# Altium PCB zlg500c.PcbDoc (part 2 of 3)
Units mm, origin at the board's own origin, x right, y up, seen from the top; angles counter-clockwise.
Board outline 135.13 x 130.56 mm, 2 copper layers (Top Layer, Bottom Layer); 79 components, 87 nets, 356 pads, 44 vias.
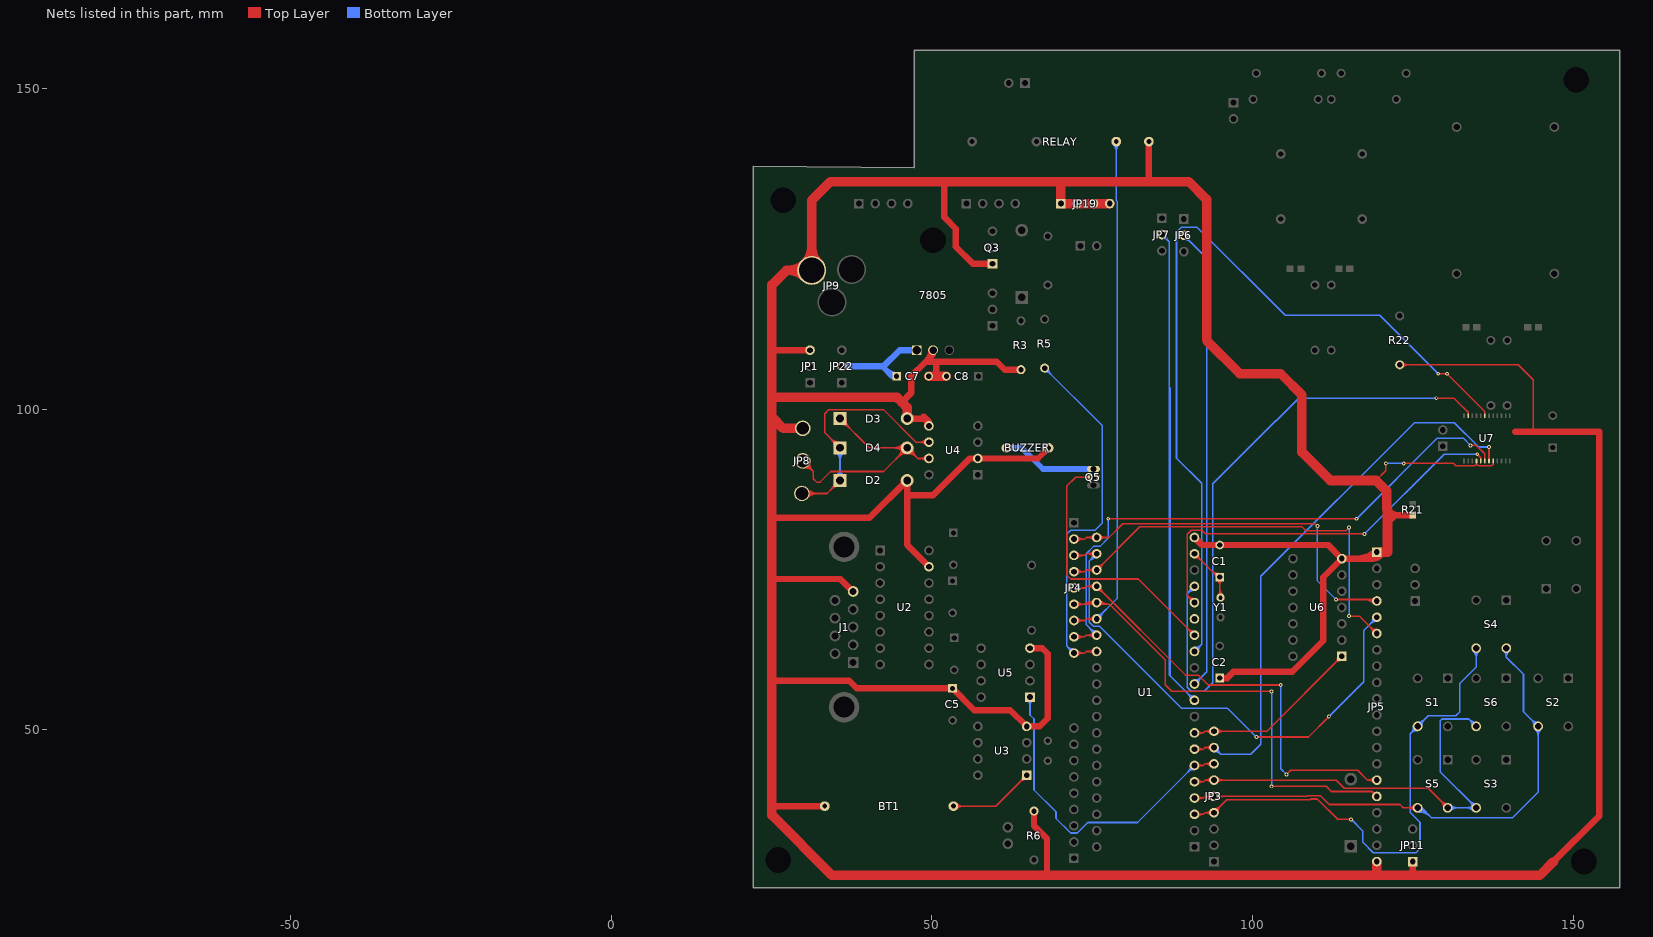
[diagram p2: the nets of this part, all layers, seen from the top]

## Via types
v1: diameter 0.6, hole 0.3, Top Layer to Bottom Layer, 43 vias
v2: diameter 1.27, hole 0.711, Top Layer to Bottom Layer, 1 vias

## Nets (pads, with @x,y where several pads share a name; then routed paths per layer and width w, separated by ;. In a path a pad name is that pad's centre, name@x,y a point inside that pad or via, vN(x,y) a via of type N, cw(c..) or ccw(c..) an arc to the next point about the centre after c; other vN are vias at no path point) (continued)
AP1.2: JP3.4 S1.3 S4.3 U1.3 | length 112.1
  Top Layer w0.254: U1.3@90.932,36.83 92.329,36.83 ; v1(115.367,36.043) 113.259,36.043 110.084,39.218 109.098,39.218 108.971,39.091 95.987,39.091 JP3.4@93.98,37.084 92.583,37.084 ; 91.759,36.83 cw(c91.759,37.573) 91.207,37.077 ccw(c91.759,37.573) 91.759,36.83 ; 91.759,36.83 ccw(c91.759,36.087) 91.207,36.583 cw(c91.759,36.087) 91.759,36.83 ; 92.329,36.83 cw(c92.329,38.085) 91.396,37.246 ccw(c92.329,38.085) 92.329,36.83 ; 92.329,36.83 ccw(c92.329,35.575) 91.396,36.414 cw(c92.329,35.575) 92.329,36.83 ; 92.329,36.83 92.583,37.084 ; 92.583,37.084 cw(c92.583,35.829) 93.516,36.668 ccw(c92.583,35.829) 92.583,37.084 ; 92.583,37.084 ccw(c92.583,38.339) 93.516,37.5 cw(c92.583,38.339) 92.583,37.084 ; 93.153,37.084 cw(c93.153,36.341) 93.705,36.837 ccw(c93.153,36.341) 93.153,37.084 ; 93.153,37.084 ccw(c93.153,37.827) 93.705,37.331 cw(c93.153,37.827) 93.153,37.084 ; 94.61,37.714 cw(c93.98,38.344) 93.98,37.453 ccw(c93.98,38.344) 94.61,37.714 ; 94.61,37.714 ccw(c95.24,37.084) 94.349,37.084 cw(c95.24,37.084) 94.61,37.714 ; 95.044,38.148 cw(c93.98,39.211) 93.98,37.707 ccw(c93.98,39.211) 95.044,38.148 ; 95.044,38.148 ccw(c96.107,37.084) 94.603,37.084 cw(c96.107,37.084) 95.044,38.148
  Bottom Layer w0.254: v1(115.367,36.043) 117.17,34.239 117.17,32.512 118.821,30.861 125.476,30.861 126.111,31.496 126.111,35.585 124.587,37.109 124.587,49.403 S1.3@125.73,50.546 127.381,52.197 131.699,52.197 132.334,52.832 132.334,57.277 134.874,59.817 S4.3@134.874,62.738 ; S1.3@125.095,50.546 cw(c123.562,50.546) 124.646,49.462 cw(c125.73,48.378) S1.3@125.73,49.911 ; S1.3@125.349,50.546 cw(c124.429,50.546) 125.08,49.896 cw(c125.73,49.245) S1.3@125.73,50.165 ; S1.3@125.73,50.927 ccw(c125.73,51.847) 126.38,51.196 ccw(c127.031,50.546) S1.3@126.111,50.546 ; S1.3@125.73,51.181 ccw(c125.73,52.714) 126.814,51.63 ccw(c127.898,50.546) S1.3@126.365,50.546 ; S4.3@134.425,62.289 cw(c133.341,61.205) 134.874,61.205 cw(c136.407,61.205) S4.3@135.323,62.289 ; S4.3@134.605,62.469 cw(c133.954,61.818) 134.874,61.818 cw(c135.794,61.818) S4.3@135.143,62.469
AP1.3: JP3.5 S2.3 S4.4 S5.3 U1.4 | length 123.9
  Top Layer w0.254: U1.4@90.932,39.37 92.329,39.37 ; S5.3@125.281,37.397 ccw(c124.197,36.313) 124.197,37.846 ccw(c124.197,39.379) S5.3@125.281,38.295 ; S5.3@125.461,37.577 ccw(c124.81,36.926) 124.81,37.846 ccw(c124.81,38.766) S5.3@125.461,38.115 ; S5.3@125.73,37.846 123.495,37.846 122.987,38.354 111.963,38.354 110.592,39.726 108.585,39.726 108.483,39.624 JP3.5@93.98,39.624 92.583,39.624 ; 91.759,39.37 cw(c91.759,40.113) 91.207,39.617 ccw(c91.759,40.113) 91.759,39.37 ; 91.759,39.37 ccw(c91.759,38.627) 91.207,39.123 cw(c91.759,38.627) 91.759,39.37 ; 92.329,39.37 cw(c92.329,40.625) 91.396,39.786 ccw(c92.329,40.625) 92.329,39.37 ; 92.329,39.37 ccw(c92.329,38.115) 91.396,38.954 cw(c92.329,38.115) 92.329,39.37 ; 92.329,39.37 92.583,39.624 ; 92.583,39.624 cw(c92.583,38.369) 93.516,39.208 ccw(c92.583,38.369) 92.583,39.624 ; 92.583,39.624 ccw(c92.583,40.879) 93.516,40.04 cw(c92.583,40.879) 92.583,39.624 ; 93.153,39.624 cw(c93.153,38.881) 93.705,39.377 ccw(c93.153,38.881) 93.153,39.624 ; 93.153,39.624 ccw(c93.153,40.367) 93.705,39.871 cw(c93.153,40.367) 93.153,39.624 ; 94.871,39.624 cw(c94.871,40.515) 94.241,39.885 ccw(c94.871,40.515) 94.871,39.624 ; 94.871,39.624 ccw(c94.871,38.733) 94.241,39.363 cw(c94.871,38.733) 94.871,39.624 ; 95.484,39.624 cw(c95.484,41.128) 94.421,40.065 ccw(c95.484,41.128) 95.484,39.624 ; 95.484,39.624 ccw(c95.484,38.12) 94.421,39.183 cw(c95.484,38.12) 95.484,39.624
  Bottom Layer w0.254: S5.3@125.73,37.211 cw(c125.73,34.145) 127.898,36.313 ; S5.3@125.73,37.465 cw(c125.73,35.012) 127.464,36.747 ; S5.3@125.73,37.719 cw(c125.73,35.879) 127.031,37.18 ; S5.3@125.73,37.846 126.365,37.846 127.889,36.322 140.589,36.322 144.526,40.259 S2.3@144.526,50.546 142.24,52.832 142.24,58.674 139.573,61.341 ; S5.3@125.73,37.973 cw(c125.73,36.747) 126.597,37.614 ; S4.4@139.155,62.26 cw(c138.354,61.341) 139.573,61.341 ; S4.4@139.322,62.451 cw(c138.842,61.9) 139.573,61.9 cw(c140.304,61.9) S4.4@139.824,62.451 ; S4.4@139.573,62.738 139.573,61.341 ; S4.4@139.991,62.26 ccw(c140.792,61.341) 139.573,61.341 ; S2.3@143.891,50.546 ccw(c142.358,50.546) 143.442,51.63 ccw(c144.526,52.714) S2.3@144.526,51.181 ; S2.3@144.077,50.097 cw(c142.993,49.013) 144.526,49.013 cw(c146.059,49.013) S2.3@144.975,50.097 ; S2.3@144.145,50.546 ccw(c143.225,50.546) 143.876,51.196 ccw(c144.526,51.847) S2.3@144.526,50.927 ; S2.3@144.257,50.277 cw(c143.606,49.626) 144.526,49.626 cw(c145.446,49.626) S2.3@144.795,50.277
AP1.4: JP3.6 S3.3 S5.4 S6.3 U1.5 | length 119.7
  Top Layer w0.254: U1.5@90.932,41.91 92.329,41.91 ; S5.4@129.794,37.846 ccw(c128.261,37.846) 129.345,38.93 ccw(c130.429,40.014) S5.4@130.429,38.481 ; S5.4@130.048,37.846 ccw(c129.128,37.846) 129.779,38.496 ccw(c130.429,39.147) S5.4@130.429,38.227 ; S5.4@130.429,37.846 127.381,40.894 114.3,40.894 113.03,42.164 JP3.6@93.98,42.164 92.583,42.164 ; 91.759,41.91 cw(c91.759,42.653) 91.207,42.157 ccw(c91.759,42.653) 91.759,41.91 ; 91.759,41.91 ccw(c91.759,41.167) 91.207,41.663 cw(c91.759,41.167) 91.759,41.91 ; 92.329,41.91 cw(c92.329,43.165) 91.396,42.326 ccw(c92.329,43.165) 92.329,41.91 ; 92.329,41.91 ccw(c92.329,40.655) 91.396,41.494 cw(c92.329,40.655) 92.329,41.91 ; 92.329,41.91 92.583,42.164 ; 92.583,42.164 cw(c92.583,40.909) 93.516,41.748 ccw(c92.583,40.909) 92.583,42.164 ; 92.583,42.164 ccw(c92.583,43.419) 93.516,42.58 cw(c92.583,43.419) 92.583,42.164 ; 93.153,42.164 cw(c93.153,41.421) 93.705,41.917 ccw(c93.153,41.421) 93.153,42.164 ; 93.153,42.164 ccw(c93.153,42.907) 93.705,42.411 cw(c93.153,42.907) 93.153,42.164 ; 94.871,42.164 cw(c94.871,43.055) 94.241,42.425 ccw(c94.871,43.055) 94.871,42.164 ; 94.871,42.164 ccw(c94.871,41.273) 94.241,41.903 cw(c94.871,41.273) 94.871,42.164 ; 95.484,42.164 cw(c95.484,43.668) 94.421,42.605 ccw(c95.484,43.668) 95.484,42.164 ; 95.484,42.164 ccw(c95.484,40.66) 94.421,41.723 cw(c95.484,40.66) 95.484,42.164
  Bottom Layer w0.254: S5.4@130.429,37.846 S3.3@134.874,37.846 129.286,43.434 129.286,51.435 129.54,51.689 133.731,51.689 S6.3@134.874,50.546 ; S6.3@134.239,50.546 ccw(c132.706,50.546) 133.79,51.63 ccw(c134.874,52.714) S6.3@134.874,51.181 ; S6.3@134.493,50.546 ccw(c133.573,50.546) 134.224,51.196 ccw(c134.874,51.847) S6.3@134.874,50.927 ; 131.349,37.846 cw(c131.349,38.766) 130.698,38.115 ccw(c131.349,38.766) 131.349,37.846 ; 131.349,37.846 ccw(c131.349,36.926) 130.698,37.577 cw(c131.349,36.926) 131.349,37.846 ; 131.962,37.846 cw(c131.962,39.379) 130.878,38.295 ccw(c131.962,39.379) 131.962,37.846 ; 131.962,37.846 ccw(c131.962,36.313) 130.878,37.397 cw(c131.962,36.313) 131.962,37.846 ; 133.341,37.846 cw(c133.341,36.313) 134.425,37.397 ccw(c133.341,36.313) 133.341,37.846 ; 133.341,37.846 ccw(c133.341,39.379) 134.425,38.295 cw(c133.341,39.379) 133.341,37.846 ; 133.79,38.93 cw(c132.706,37.846) 134.239,37.846 ccw(c132.706,37.846) 133.79,38.93 ; 133.79,38.93 ccw(c134.874,40.014) 134.874,38.481 cw(c134.874,40.014) 133.79,38.93 ; 133.954,37.846 cw(c133.954,36.926) 134.605,37.577 ccw(c133.954,36.926) 133.954,37.846 ; 133.954,37.846 ccw(c133.954,38.766) 134.605,38.115 cw(c133.954,38.766) 133.954,37.846 ; 134.224,38.496 cw(c133.573,37.846) 134.493,37.846 ccw(c133.573,37.846) 134.224,38.496 ; 134.224,38.496 ccw(c134.874,39.147) 134.874,38.227 cw(c134.874,39.147) 134.224,38.496
AP1.5: JP3.7 U1.6 U5.1 | length 75.4
  Top Layer w0.254: U1.6@90.932,44.45 92.329,44.45 ; JP3.7@93.98,44.704 92.583,44.704 ; 91.759,44.45 cw(c91.759,45.193) 91.207,44.697 ccw(c91.759,45.193) 91.759,44.45 ; 91.759,44.45 ccw(c91.759,43.707) 91.207,44.203 cw(c91.759,43.707) 91.759,44.45 ; 92.329,44.45 cw(c92.329,45.705) 91.396,44.866 ccw(c92.329,45.705) 92.329,44.45 ; 92.329,44.45 ccw(c92.329,43.195) 91.396,44.034 cw(c92.329,43.195) 92.329,44.45 ; 92.329,44.45 92.583,44.704 ; 92.583,44.704 cw(c92.583,43.449) 93.516,44.288 ccw(c92.583,43.449) 92.583,44.704 ; 92.583,44.704 ccw(c92.583,45.959) 93.516,45.12 cw(c92.583,45.959) 92.583,44.704 ; 93.153,44.704 cw(c93.153,43.961) 93.705,44.457 ccw(c93.153,43.961) 93.153,44.704 ; 93.153,44.704 ccw(c93.153,45.447) 93.705,44.951 cw(c93.153,45.447) 93.153,44.704
  Bottom Layer w0.254: U5.1@64.837,54.677 cw(c63.774,53.614) 65.278,53.614 cw(c66.782,53.614) U5.1@65.719,54.677 ; U5.1@65.017,54.857 cw(c64.387,54.227) 65.278,54.227 cw(c66.169,54.227) U5.1@65.539,54.857 ; U5.1@65.278,55.118 65.278,52.324 65.913,51.689 65.913,40.64 69.342,37.211 69.342,36.195 71.628,33.909 72.644,33.909 74.295,35.56 82.042,35.56 U1.6@90.932,44.45 ; 89.868,43.386 cw(c90.932,42.323) 90.932,43.827 ccw(c90.932,42.323) 89.868,43.386 ; 89.868,43.386 ccw(c88.805,44.45) 90.309,44.45 cw(c88.805,44.45) 89.868,43.386 ; 90.302,43.82 cw(c90.932,43.19) 90.932,44.081 ccw(c90.932,43.19) 90.302,43.82 ; 90.302,43.82 ccw(c89.672,44.45) 90.563,44.45 cw(c89.672,44.45) 90.302,43.82
AP1.6: JP3.8 U1.7 U7.7 | length 107.9
  Top Layer w0.254: U1.7@90.932,46.99 92.329,46.99 ; JP3.8@93.98,47.244 92.583,47.244 ; U7.7@136.869,91.948 v1(136.869,94.107) ; 91.759,46.99 cw(c91.759,47.733) 91.207,47.237 ccw(c91.759,47.733) 91.759,46.99 ; 91.759,46.99 ccw(c91.759,46.247) 91.207,46.743 cw(c91.759,46.247) 91.759,46.99 ; 92.329,46.99 cw(c92.329,48.245) 91.396,47.406 ccw(c92.329,48.245) 92.329,46.99 ; 92.329,46.99 ccw(c92.329,45.735) 91.396,46.574 cw(c92.329,45.735) 92.329,46.99 ; 92.329,46.99 92.583,47.244 ; 92.583,47.244 cw(c92.583,45.989) 93.516,46.828 ccw(c92.583,45.989) 92.583,47.244 ; 92.583,47.244 ccw(c92.583,48.499) 93.516,47.66 cw(c92.583,48.499) 92.583,47.244 ; 93.153,47.244 cw(c93.153,46.501) 93.705,46.997 ccw(c93.153,46.501) 93.153,47.244 ; 93.153,47.244 ccw(c93.153,47.987) 93.705,47.491 cw(c93.153,47.987) 93.153,47.244
  Bottom Layer w0.254: JP3.8@93.98,47.244 95.047,46.177 99.695,46.177 101.27,47.752 101.27,73.939 125.247,97.917 131.445,97.917 135.255,94.107 v1(136.869,94.107) ; 94.61,46.614 cw(c95.24,47.244) 94.349,47.244 ccw(c95.24,47.244) 94.61,46.614 ; 94.61,46.614 ccw(c93.98,45.984) 93.98,46.875 cw(c93.98,45.984) 94.61,46.614 ; 95.044,46.18 cw(c96.107,47.244) 94.603,47.244 ccw(c96.107,47.244) 95.044,46.18 ; 95.044,46.18 ccw(c93.98,45.117) 93.98,46.621 cw(c93.98,45.117) 95.044,46.18
AP1.7: JP3.9 U1.8 U6.1 | length 56.4
  Top Layer w0.254: U1.8@90.932,49.53 92.329,49.53 ; U6.1@113.919,61.468 102.235,49.784 JP3.9@93.98,49.784 92.583,49.784 ; 91.759,49.53 cw(c91.759,50.273) 91.207,49.777 ccw(c91.759,50.273) 91.759,49.53 ; 91.759,49.53 ccw(c91.759,48.787) 91.207,49.283 cw(c91.759,48.787) 91.759,49.53 ; 92.329,49.53 cw(c92.329,50.785) 91.396,49.946 ccw(c92.329,50.785) 92.329,49.53 ; 92.329,49.53 ccw(c92.329,48.275) 91.396,49.114 cw(c92.329,48.275) 92.329,49.53 ; 92.329,49.53 92.583,49.784 ; 92.583,49.784 cw(c92.583,48.529) 93.516,49.368 ccw(c92.583,48.529) 92.583,49.784 ; 92.583,49.784 ccw(c92.583,51.039) 93.516,50.2 cw(c92.583,51.039) 92.583,49.784 ; 93.153,49.784 cw(c93.153,49.041) 93.705,49.537 ccw(c93.153,49.041) 93.153,49.784 ; 93.153,49.784 ccw(c93.153,50.527) 93.705,50.031 cw(c93.153,50.527) 93.153,49.784 ; 94.871,49.784 cw(c94.871,50.675) 94.241,50.045 ccw(c94.871,50.675) 94.871,49.784 ; 94.871,49.784 ccw(c94.871,48.893) 94.241,49.523 cw(c94.871,48.893) 94.871,49.784 ; 95.484,49.784 cw(c95.484,51.288) 94.421,50.225 ccw(c95.484,51.288) 95.484,49.784 ; 95.484,49.784 ccw(c95.484,48.28) 94.421,49.343 cw(c95.484,48.28) 95.484,49.784 ; 112.855,60.404 cw(c113.919,59.341) 113.919,60.845 ccw(c113.919,59.341) 112.855,60.404 ; 112.855,60.404 ccw(c111.792,61.468) 113.296,61.468 cw(c111.792,61.468) 112.855,60.404 ; U6.1@113.289,60.838 cw(c113.919,60.208) 113.919,61.099 ccw(c113.919,60.208) U6.1@113.289,60.838 ; U6.1@113.289,60.838 ccw(c112.659,61.468) 113.55,61.468 cw(c112.659,61.468) U6.1@113.289,60.838
AP2.0: JP4.2 JP5.4 U1.21 | length 74
  Top Layer w0.254: JP4.2@72.136,79.756 73.787,79.756 74.041,80.01 U1.21@75.692,80.01 77.597,80.01 79.756,82.169 109.728,82.169 v1(110.109,81.788) ; JP4.2@72.397,79.495 cw(c73.027,78.865) 73.027,79.756 cw(c73.027,80.647) JP4.2@72.397,80.017 ; JP4.2@72.577,79.315 cw(c73.64,78.252) 73.64,79.756 cw(c73.64,81.26) JP4.2@72.577,80.197 ; U1.21@75.251,79.569 ccw(c74.188,78.506) 74.188,80.01 ccw(c74.188,81.514) U1.21@75.251,80.451 ; U1.21@75.431,79.749 ccw(c74.801,79.119) 74.801,80.01 ccw(c74.801,80.901) U1.21@75.431,80.271 ; U1.21@75.953,79.749 cw(c76.583,79.119) 76.583,80.01 cw(c76.583,80.901) U1.21@75.953,80.271 ; U1.21@76.133,79.569 cw(c77.196,78.506) 77.196,80.01 cw(c77.196,81.514) U1.21@76.133,80.451 ; v1(113.005,70.333) 119.151,70.333 JP5.4@119.38,70.104 ; 117.324,70.333 cw(c117.324,68.048) JP5.4@118.939,69.663 ; 117.937,70.333 cw(c117.937,68.661) JP5.4@119.119,69.843 ; 118.428,70.333 ccw(c118.428,71.056) JP5.4@118.939,70.545 ; 118.55,70.333 cw(c118.55,69.274) JP5.4@119.299,70.023
  Bottom Layer w0.254: v1(110.109,81.788) 110.109,73.228 v1(113.005,70.333)
AP2.1: JP4.3 JP5.5 U1.22 | length 105.8
  Top Layer w0.254: JP4.3@72.136,77.216 73.787,77.216 74.041,77.47 U1.22@75.692,77.47 ; v1(100.584,48.895) 108.712,48.895 v1(111.887,52.07) ; 73.027,77.216 cw(c73.027,78.107) 72.397,77.477 ccw(c73.027,78.107) 73.027,77.216 ; 73.027,77.216 ccw(c73.027,76.325) 72.397,76.955 cw(c73.027,76.325) 73.027,77.216 ; 73.64,77.216 cw(c73.64,78.72) 72.577,77.657 ccw(c73.64,78.72) 73.64,77.216 ; 73.64,77.216 ccw(c73.64,75.712) 72.577,76.775 cw(c73.64,75.712) 73.64,77.216 ; 74.188,77.47 cw(c74.188,75.966) 75.251,77.029 ccw(c74.188,75.966) 74.188,77.47 ; 74.188,77.47 ccw(c74.188,78.974) 75.251,77.911 cw(c74.188,78.974) 74.188,77.47 ; 74.801,77.47 cw(c74.801,76.579) 75.431,77.209 ccw(c74.801,76.579) 74.801,77.47 ; 74.801,77.47 ccw(c74.801,78.361) 75.431,77.731 cw(c74.801,78.361) 74.801,77.47
  Bottom Layer w0.254: U1.22@75.069,77.47 cw(c73.565,77.47) 74.628,76.406 cw(c75.692,75.343) U1.22@75.692,76.847 ; U1.22@75.323,77.47 cw(c74.432,77.47) 75.062,76.84 cw(c75.692,76.21) U1.22@75.692,77.101 ; U1.22@75.692,77.47 74.549,76.327 74.549,66.802 75.184,66.167 76.124,66.167 88.9,53.391 96.088,53.391 v1(100.584,48.895) ; v1(111.887,52.07) 117.323,57.506 117.323,65.507 JP5.5@119.38,67.564 ; 118.316,66.5 cw(c119.38,65.437) 119.38,66.941 ccw(c119.38,65.437) 118.316,66.5 ; 118.316,66.5 ccw(c117.253,67.564) 118.757,67.564 cw(c117.253,67.564) 118.316,66.5 ; 118.75,66.934 cw(c119.38,66.304) 119.38,67.195 ccw(c119.38,66.304) 118.75,66.934 ; 118.75,66.934 ccw(c118.12,67.564) 119.011,67.564 cw(c118.12,67.564) 118.75,66.934
AP2.2: JP4.4 JP5.6 U1.23 | length 88.1
  Top Layer w0.254: JP4.4@72.136,74.676 73.787,74.676 74.041,74.93 U1.23@75.692,74.93 82.423,81.661 107.721,81.661 108.306,81.077 114.579,81.077 v1(115.062,81.559) ; U1.23@75.692,75.299 ccw(c75.692,76.19) 76.322,75.56 ccw(c76.952,74.93) U1.23@76.061,74.93 ; U1.23@75.692,75.553 ccw(c75.692,77.057) 76.756,75.994 ccw(c77.819,74.93) U1.23@76.315,74.93 ; v1(115.062,67.742) 116.662,67.742 JP5.6@119.38,65.024 ; JP5.6@118.757,65.024 ccw(c117.253,65.024) 118.316,66.088 ccw(c119.38,67.151) JP5.6@119.38,65.647 ; JP5.6@119.011,65.024 ccw(c118.12,65.024) 118.75,65.654 ccw(c119.38,66.284) JP5.6@119.38,65.393 ; 73.027,74.676 cw(c73.027,75.567) 72.397,74.937 ccw(c73.027,75.567) 73.027,74.676 ; 73.027,74.676 ccw(c73.027,73.785) 72.397,74.415 cw(c73.027,73.785) 73.027,74.676 ; 73.64,74.676 cw(c73.64,76.18) 72.577,75.117 ccw(c73.64,76.18) 73.64,74.676 ; 73.64,74.676 ccw(c73.64,73.172) 72.577,74.235 cw(c73.64,73.172) 73.64,74.676 ; 74.188,74.93 cw(c74.188,73.426) 75.251,74.489 ccw(c74.188,73.426) 74.188,74.93 ; 74.188,74.93 ccw(c74.188,76.434) 75.251,75.371 cw(c74.188,76.434) 74.188,74.93 ; 74.801,74.93 cw(c74.801,74.039) 75.431,74.669 ccw(c74.801,74.039) 74.801,74.93 ; 74.801,74.93 ccw(c74.801,75.821) 75.431,75.191 cw(c74.801,75.821) 74.801,74.93
  Bottom Layer w0.254: v1(115.062,67.742) v1(115.062,81.559)
AP2.3: JP4.5 JP5.15 U1.24 | length 94
  Top Layer w0.254: JP4.5@72.136,72.136 73.787,72.136 74.041,72.39 U1.24@75.692,72.39 89.535,58.547 91.542,58.547 93.091,56.998 v1(104.394,56.998) ; U1.24@75.692,71.767 cw(c75.692,70.263) 76.756,71.326 cw(c77.819,72.39) U1.24@76.315,72.39 ; U1.24@75.692,72.021 cw(c75.692,71.13) 76.322,71.76 cw(c76.952,72.39) U1.24@76.061,72.39 ; v1(105.283,43.053) 105.943,43.713 116.383,43.713 117.932,42.164 ; JP5.15@119.38,42.164 117.932,42.164 ; 73.027,72.136 cw(c73.027,73.027) 72.397,72.397 ccw(c73.027,73.027) 73.027,72.136 ; 73.027,72.136 ccw(c73.027,71.245) 72.397,71.875 cw(c73.027,71.245) 73.027,72.136 ; 73.64,72.136 cw(c73.64,73.64) 72.577,72.577 ccw(c73.64,73.64) 73.64,72.136 ; 73.64,72.136 ccw(c73.64,70.632) 72.577,71.695 cw(c73.64,70.632) 73.64,72.136 ; 74.188,72.39 cw(c74.188,70.886) 75.251,71.949 ccw(c74.188,70.886) 74.188,72.39 ; 74.188,72.39 ccw(c74.188,73.894) 75.251,72.831 cw(c74.188,73.894) 74.188,72.39 ; 74.801,72.39 cw(c74.801,71.499) 75.431,72.129 ccw(c74.801,71.499) 74.801,72.39 ; 74.801,72.39 ccw(c74.801,73.281) 75.431,72.651 cw(c74.801,73.281) 74.801,72.39 ; 117.932,42.164 cw(c117.932,40.793) 118.928,41.736 ccw(c117.932,40.793) 117.932,42.164 ; 117.932,42.164 ccw(c117.932,43.535) 118.928,42.592 cw(c117.932,43.535) 117.932,42.164 ; 118.523,42.164 cw(c118.523,41.352) 119.112,41.91 ccw(c118.523,41.352) 118.523,42.164 ; 118.523,42.164 ccw(c118.523,42.976) 119.112,42.418 cw(c118.523,42.976) 118.523,42.164
  Bottom Layer w0.254: v1(104.394,56.998) 104.394,43.942 v1(105.283,43.053)
AP2.4: JP4.6 JP5.16 U1.25 | length 107.2
  Top Layer w0.254: JP4.6@72.136,69.596 73.787,69.596 ; U1.25@75.692,69.85 74.041,69.85 73.787,69.596 ; v1(102.972,41.199) 111.475,41.199 112.288,40.386 118.618,40.386 ; v1(102.972,56.007) 87.376,56.007 86.36,57.023 86.36,60.909 77.673,69.596 ; JP5.16@119.38,39.624 118.618,40.386 ; 73.027,69.596 cw(c73.027,70.487) 72.397,69.857 ccw(c73.027,70.487) 73.027,69.596 ; 73.027,69.596 ccw(c73.027,68.705) 72.397,69.335 cw(c73.027,68.705) 73.027,69.596 ; 73.64,69.596 cw(c73.64,71.1) 72.577,70.037 ccw(c73.64,71.1) 73.64,69.596 ; 73.64,69.596 ccw(c73.64,68.092) 72.577,69.155 cw(c73.64,68.092) 73.64,69.596 ; 73.787,69.596 ccw(c73.787,71.48) 75.219,70.255 cw(c73.787,71.48) 73.787,69.596 ; 73.787,69.596 75.692,69.596 77.673,69.596 ; 74.188,69.85 cw(c74.188,68.346) U1.25@75.251,69.409 ; 74.188,69.85 ccw(c74.188,71.354) 75.251,70.291 cw(c74.188,71.354) 74.188,69.85 ; 74.188,69.85 cw(c74.188,68.346) U1.25@75.251,69.409 ; 74.801,69.85 cw(c74.801,68.959) 75.431,69.589 ccw(c74.801,68.959) 74.801,69.85 ; 74.801,69.85 ccw(c74.801,70.741) 75.431,70.111 cw(c74.801,70.741) 74.801,69.85 ; U1.25@75.251,69.409 ccw(c74.801,68.959) 74.801,69.596 cw(c74.801,68.959) U1.25@75.251,69.409 ; 77.673,69.596 cw(c77.673,71.649) 76.153,70.269 ccw(c77.673,71.649) 77.673,69.596 ; 118.618,40.386 cw(c118.179,39.947) 118.778,39.786 ccw(c118.179,39.947) 118.618,40.386 ; 118.618,40.386 ccw(c119.057,40.825) 119.218,40.226 cw(c119.057,40.825) 118.618,40.386 ; 74.339,69.596 ccw(c74.339,71.008) 75.412,70.09 cw(c74.339,71.008) 74.339,69.596 ; 74.891,69.596 ccw(c74.891,70.536) 75.605,69.925 cw(c74.891,70.536) 74.891,69.596 ; U1.25@75.777,69.927 ccw(c76.526,70.607) 76.526,69.596 cw(c76.526,70.607) U1.25@75.777,69.927 ; U1.25@75.965,70.098 ccw(c77.099,71.128) 77.099,69.596 cw(c77.099,71.128) U1.25@75.965,70.098 ; U1.25@76.133,69.409 cw(c76.583,68.959) 76.583,69.596 ccw(c76.583,68.959) U1.25@76.133,69.409
  Bottom Layer w0.254: v1(102.972,41.199) v1(102.972,56.007)
AP2.5: JP4.7 RELAY.1 U1.26 | length 106
  Top Layer w0.254: JP4.7@72.136,67.056 73.787,67.056 74.041,67.31 U1.26@75.692,67.31 ; 73.027,67.056 cw(c73.027,67.947) 72.397,67.317 ccw(c73.027,67.947) 73.027,67.056 ; 73.027,67.056 ccw(c73.027,66.165) 72.397,66.795 cw(c73.027,66.165) 73.027,67.056 ; 73.64,67.056 cw(c73.64,68.56) 72.577,67.497 ccw(c73.64,68.56) 73.64,67.056 ; 73.64,67.056 ccw(c73.64,65.552) 72.577,66.615 cw(c73.64,65.552) 73.64,67.056 ; 74.188,67.31 cw(c74.188,65.806) 75.251,66.869 ccw(c74.188,65.806) 74.188,67.31 ; 74.188,67.31 ccw(c74.188,68.814) 75.251,67.751 cw(c74.188,68.814) 74.188,67.31 ; 74.801,67.31 cw(c74.801,66.419) 75.431,67.049 ccw(c74.801,66.419) 74.801,67.31 ; 74.801,67.31 ccw(c74.801,68.201) 75.431,67.571 cw(c74.801,68.201) 74.801,67.31
  Bottom Layer w0.254: U1.26@75.692,67.31 78.867,70.485 78.867,132.461 78.74,132.588 RELAY.1@78.74,141.732 ; U1.26@75.692,67.679 ccw(c75.692,68.57) 76.322,67.94 ccw(c76.952,67.31) U1.26@76.061,67.31 ; U1.26@75.692,67.933 ccw(c75.692,69.437) 76.756,68.374 ccw(c77.819,67.31) U1.26@76.315,67.31 ; 78.74,140.199 cw(c80.273,140.199) 79.189,141.283 ccw(c80.273,140.199) 78.74,140.199 ; 78.74,140.199 ccw(c77.207,140.199) 78.291,141.283 cw(c77.207,140.199) 78.74,140.199 ; 78.74,140.812 cw(c79.66,140.812) 79.009,141.463 ccw(c79.66,140.812) 78.74,140.812 ; 78.74,140.812 ccw(c77.82,140.812) 78.471,141.463 cw(c77.82,140.812) 78.74,140.812
AP2.6: JP4.8 U1.27 U7.6 | length 113.1
  Top Layer w0.254: JP4.8@72.136,64.516 73.787,64.516 74.041,64.77 U1.27@75.692,64.77 ; v1(77.495,82.931) v1(116.23,82.931) ; v1(133.985,94.361) 134.899,94.361 136.219,93.041 U7.6@136.219,91.948 ; 73.027,64.516 cw(c73.027,65.407) 72.397,64.777 ccw(c73.027,65.407) 73.027,64.516 ; 73.027,64.516 ccw(c73.027,63.625) 72.397,64.255 cw(c73.027,63.625) 73.027,64.516 ; 73.64,64.516 cw(c73.64,66.02) 72.577,64.957 ccw(c73.64,66.02) 73.64,64.516 ; 73.64,64.516 ccw(c73.64,63.012) 72.577,64.075 cw(c73.64,63.012) 73.64,64.516 ; 74.188,64.77 cw(c74.188,63.266) 75.251,64.329 ccw(c74.188,63.266) 74.188,64.77 ; 74.188,64.77 ccw(c74.188,66.274) 75.251,65.211 cw(c74.188,66.274) 74.188,64.77 ; 74.801,64.77 cw(c74.801,63.879) 75.431,64.509 ccw(c74.801,63.879) 74.801,64.77 ; 74.801,64.77 ccw(c74.801,65.661) 75.431,65.031 cw(c74.801,65.661) 74.801,64.77
  Bottom Layer w0.254: U1.27@75.692,64.77 74.041,66.421 74.041,77.47 75.184,78.613 76.2,78.613 77.495,79.908 v1(77.495,82.931) ; v1(116.23,82.931) 128.803,95.504 132.842,95.504 v1(133.985,94.361) ; 74.628,65.834 cw(c73.565,64.77) 75.069,64.77 ccw(c73.565,64.77) 74.628,65.834 ; 74.628,65.834 ccw(c75.692,66.897) 75.692,65.393 cw(c75.692,66.897) 74.628,65.834 ; 75.062,65.4 cw(c74.432,64.77) 75.323,64.77 ccw(c74.432,64.77) 75.062,65.4 ; 75.062,65.4 ccw(c75.692,66.03) 75.692,65.139 cw(c75.692,66.03) 75.062,65.4
AP2.7: JP4.9 R5.2 U1.28 | length 82.8
  Top Layer w0.254: JP4.9@72.136,61.976 73.787,61.976 74.041,62.23 U1.28@75.692,62.23 ; 73.027,61.976 cw(c73.027,62.867) 72.397,62.237 ccw(c73.027,62.867) 73.027,61.976 ; 73.027,61.976 ccw(c73.027,61.085) 72.397,61.715 cw(c73.027,61.085) 73.027,61.976 ; 73.64,61.976 cw(c73.64,63.48) 72.577,62.417 ccw(c73.64,63.48) 73.64,61.976 ; 73.64,61.976 ccw(c73.64,60.472) 72.577,61.535 cw(c73.64,60.472) 73.64,61.976 ; 74.188,62.23 cw(c74.188,60.726) 75.251,61.789 ccw(c74.188,60.726) 74.188,62.23 ; 74.188,62.23 ccw(c74.188,63.734) 75.251,62.671 cw(c74.188,63.734) 74.188,62.23 ; 74.801,62.23 cw(c74.801,61.339) 75.431,61.969 ccw(c74.801,61.339) 74.801,62.23 ; 74.801,62.23 ccw(c74.801,63.121) 75.431,62.491 cw(c74.801,63.121) 74.801,62.23
  Bottom Layer w0.254: R5.2@67.564,105.853 cw(c67.564,104.47) 68.542,105.448 cw(c69.52,106.426) R5.2@68.137,106.426 ; R5.2@67.564,106.107 cw(c67.564,105.337) 68.109,105.881 cw(c68.653,106.426) R5.2@67.883,106.426 ; R5.2@67.564,106.426 76.581,97.409 76.581,82.296 75.438,81.153 71.628,81.153 70.993,80.518 70.993,63.119 JP4.9@72.136,61.976 ; 71.072,63.04 cw(c70.009,61.976) 71.513,61.976 ccw(c70.009,61.976) 71.072,63.04 ; 71.072,63.04 ccw(c72.136,64.103) 72.136,62.599 cw(c72.136,64.103) 71.072,63.04 ; 71.506,62.606 cw(c70.876,61.976) 71.767,61.976 ccw(c70.876,61.976) 71.506,62.606 ; 71.506,62.606 ccw(c72.136,63.236) 72.136,62.345 cw(c72.136,63.236) 71.506,62.606
AP3.3: U1.13 U7.19 | length 136
  Top Layer w0.254: v1(128.956,105.537) v1(130.326,105.537) 136.219,99.644 U7.19@136.219,98.998
  Bottom Layer w0.254: U1.13@90.932,62.23 92.075,63.373 92.075,88.443 88.138,92.38 88.138,127.635 88.9,128.397 91.338,128.397 105.08,114.656 119.837,114.656 v1(128.956,105.537) ; 91.562,62.86 cw(c90.932,63.49) 90.932,62.599 ccw(c90.932,63.49) 91.562,62.86 ; 91.562,62.86 ccw(c92.192,62.23) 91.301,62.23 cw(c92.192,62.23) 91.562,62.86 ; 91.996,63.294 cw(c90.932,64.357) 90.932,62.853 ccw(c90.932,64.357) 91.996,63.294 ; 91.996,63.294 ccw(c93.059,62.23) 91.555,62.23 cw(c93.059,62.23) 91.996,63.294
AP3.4: Q5.2 U1.14 | length 47.6
  Top Layer w0.254: Q5.2@74.42,89.144 ccw(c73.784,88.508) 73.784,89.408 ccw(c73.784,90.308) Q5.2@74.42,89.672 ; Q5.2@75.184,89.408 72.415,89.408 70.993,87.986 70.993,74.168 71.628,73.533 82.169,73.533 U1.14@90.932,64.77 ; U1.14@90.309,64.77 ccw(c88.805,64.77) 89.868,65.834 ccw(c90.932,66.897) U1.14@90.932,65.393 ; U1.14@90.563,64.77 ccw(c89.672,64.77) 90.302,65.4 ccw(c90.932,66.03) U1.14@90.932,65.139
AP3.5: U1.15
ARD: U1.17 U7.23 | length 102.8
  Top Layer w0.254: v1(128.651,101.727) 131.42,101.727 132.969,100.178 ; 133.096,100.178 132.969,100.178 ; U7.23@133.619,98.998 133.619,99.528 132.969,100.178
  Bottom Layer w0.254: U1.17@90.309,72.39 cw(c88.805,72.39) 89.868,71.326 cw(c90.932,70.263) U1.17@90.932,71.767 ; U1.17@90.563,72.39 cw(c89.672,72.39) 90.302,71.76 cw(c90.932,71.13) U1.17@90.932,72.021 ; U1.17@90.932,72.39 89.789,71.247 89.789,56.642 90.424,56.007 92.456,56.007 93.802,57.353 93.802,88.392 103.632,98.222 103.683,98.222 107.188,101.727 v1(128.651,101.727)
ARXD: JP7.2 U1.10 | length 127.2
  Bottom Layer w0.254: JP7.2@85.852,126.631 cw(c85.852,125.127) 86.916,126.19 cw(c87.979,127.254) JP7.2@86.475,127.254 ; JP7.2@85.852,126.885 cw(c85.852,125.994) 86.482,126.624 cw(c87.112,127.254) JP7.2@86.221,127.254 ; JP7.2@85.852,127.254 86.995,126.111 86.995,58.547 87.122,58.42 ; 87.122,103.378 87.122,58.42 ; U1.10@90.309,54.61 ccw(c88.805,54.61) 89.868,55.674 ccw(c90.932,56.737) U1.10@90.932,55.233 ; U1.10@90.563,54.61 ccw(c89.672,54.61) 90.302,55.24 ccw(c90.932,55.87) U1.10@90.932,54.979 ; U1.10@90.932,54.61 87.122,58.42
ATXD: JP6.2 U1.11 | length 87.3
  Bottom Layer w0.254: JP6.2@89.281,127.127 92.837,123.571 92.837,59.055 U1.11@90.932,57.15 ; 89.911,126.497 cw(c90.541,127.127) 89.65,127.127 ccw(c90.541,127.127) 89.911,126.497 ; 89.911,126.497 ccw(c89.281,125.867) 89.281,126.758 cw(c89.281,125.867) 89.911,126.497 ; 90.345,126.063 cw(c91.408,127.127) 89.904,127.127 ccw(c91.408,127.127) 90.345,126.063 ; 90.345,126.063 ccw(c89.281,125) 89.281,126.504 cw(c89.281,125) 90.345,126.063 ; 91.562,57.78 cw(c90.932,58.41) 90.932,57.519 ccw(c90.932,58.41) 91.562,57.78 ; 91.562,57.78 ccw(c92.192,57.15) 91.301,57.15 cw(c92.192,57.15) 91.562,57.78 ; 91.996,58.214 cw(c90.932,59.277) 90.932,57.773 ccw(c90.932,59.277) 91.996,58.214 ; 91.996,58.214 ccw(c93.059,57.15) 91.555,57.15 cw(c93.059,57.15) 91.996,58.214
AWR: U1.16 U7.5 | length 67.1
  Top Layer w0.254: U1.16@90.309,69.85 ccw(c88.805,69.85) 89.868,70.914 ccw(c90.932,71.977) U1.16@90.932,70.473 ; U1.16@90.563,69.85 ccw(c89.672,69.85) 90.302,70.48 ccw(c90.932,71.11) U1.16@90.932,70.219 ; U1.16@90.932,69.85 89.789,70.993 89.789,80.506 90.436,81.153 92.063,81.153 92.647,80.569 v1(117.45,80.569) ; v1(135.036,92.989) 135.569,92.456 U7.5@135.569,91.948
  Bottom Layer w0.254: v1(117.45,80.569) 129.87,92.989 v1(135.036,92.989)
DATA1+: D2.2 D4.2 JP8.1 U4.6 | length 72.7
  Top Layer w0.254: JP8.1@29.718,86.868 33.632,86.868 D2.2@35.664,88.9 ; JP8.1@30.126,86.46 cw(c31.111,85.475) 31.111,86.868 cw(c31.111,88.261) JP8.1@30.126,87.276 ; JP8.1@30.306,86.28 cw(c31.724,84.862) 31.724,86.868 cw(c31.724,88.874) JP8.1@30.306,87.456 ; JP8.1@30.485,86.101 cw(c32.337,84.249) 32.337,86.868 cw(c32.337,89.487) JP8.1@30.485,87.635 ; D2.2@34.791,88.9 cw(c32.683,88.9) 34.174,87.41 cw(c35.664,85.919) D2.2@35.664,88.027 ; D4.2@34.791,93.98 ccw(c32.683,93.98) 34.174,95.47 ccw(c35.664,96.961) D4.2@35.664,94.853 ; D2.2@35.045,88.9 cw(c33.551,88.9) 34.607,87.843 cw(c35.664,86.787) D2.2@35.664,88.281 ; D4.2@35.045,93.98 ccw(c33.551,93.98) 34.607,95.037 ccw(c35.664,96.093) D4.2@35.664,94.599 ; D4.2@35.664,93.98 33.274,96.37 33.274,99.314 33.909,99.949 42.443,99.949 47.523,94.869 U4.6@49.53,94.869 ; U4.6@49.089,94.428 ccw(c48.026,93.365) 48.026,94.869 ccw(c48.026,96.373) U4.6@49.089,95.31 ; U4.6@49.269,94.608 ccw(c48.639,93.978) 48.639,94.869 ccw(c48.639,95.76) U4.6@49.269,95.13
  Bottom Layer w0.254: D2.2@35.047,89.517 ccw(c33.556,91.008) 35.664,91.008 ccw(c37.772,91.008) D2.2@36.281,89.517 ; D4.2@35.047,93.363 cw(c33.556,91.872) 35.664,91.872 cw(c37.772,91.872) D4.2@36.281,93.363 ; D2.2@35.226,89.338 ccw(c34.17,90.394) 35.664,90.394 ccw(c37.158,90.394) D2.2@36.102,89.338 ; D4.2@35.226,93.542 cw(c34.17,92.486) 35.664,92.486 cw(c37.158,92.486) D4.2@36.102,93.542 ; D2.2@35.664,88.9 D4.2@35.664,93.98
DATA1-: D3.2 D4.1 JP8.2 U4.7 | length 71.2
  Top Layer w0.254: JP8.2@29.845,91.948 31.496,90.297 ; JP8.2@29.894,91.373 cw(c29.982,90.329) 30.723,91.07 cw(c31.464,91.811) JP8.2@30.42,91.899 ; JP8.2@29.915,91.12 cw(c30.043,89.617) 31.109,90.684 cw(c32.176,91.75) JP8.2@30.673,91.878 ; JP8.2@29.937,90.867 cw(c30.103,88.904) 31.496,90.297 ; JP8.2@30.926,91.856 ccw(c32.889,91.69) 31.496,90.297 ; D3.2@35.664,97.679 cw(c35.664,95.571) 37.154,97.062 cw(c38.645,98.552) D3.2@36.537,98.552 ; D3.2@35.664,97.933 cw(c35.664,96.439) 36.721,97.495 cw(c37.777,98.552) D3.2@36.283,98.552 ; D3.2@35.664,98.552 40.236,93.98 D4.1@46.124,93.98 ; D4.1@45.251,93.98 cw(c43.143,93.98) 44.634,92.49 cw(c46.124,90.999) 46.124,93.107 cw(c46.124,90.999) 47.614,92.49 cw(c49.105,93.98) D4.1@46.997,93.98 ; D4.1@45.505,93.98 cw(c44.011,93.98) 45.067,92.923 cw(c46.124,91.867) 46.124,93.361 cw(c46.124,91.867) 47.181,92.923 cw(c48.237,93.98) D4.1@46.743,93.98 ; D4.1@45.507,93.363 ccw(c44.016,91.872) 44.016,93.98 ccw(c44.016,96.088) D4.1@45.507,94.597 ; D4.1@45.686,93.542 ccw(c44.63,92.486) 44.63,93.98 ccw(c44.63,95.474) D4.1@45.686,94.418 ; U4.7@49.089,91.888 ccw(c48.026,90.825) 48.026,92.329 ccw(c48.026,93.833) U4.7@49.089,92.77 ; U4.7@49.269,92.068 ccw(c48.639,91.438) 48.639,92.329 ccw(c48.639,93.22) U4.7@49.269,92.59 ; U4.7@49.53,92.329 47.775,92.329 D4.1@46.124,93.98 ; 31.496,90.297 31.496,89.154 32.004,88.646 32.537,88.646 34.188,90.297 42.441,90.297 D4.1@46.124,93.98
GND: 7805.1 BT1.2 BUZZER.0 C1.2 C2.1 C5.1 C7.2 C8.2 D2.1 D3.1 J1.5 JP1.3 JP5.1 JP5.20 JP8.3 JP9.2 JP11.1 JP19.1 JP19.2 JP19.3 JP19.4 Q3.1 R3.1 R6.1 R21.1 R22.2 RELAY.0 U1.20 U2.15 U3.4 U4.2 U4.5 U5.4 U6.7 U7.4 U7.8 | length 921.2
  Top Layer w0.254: JP19.1@70.104,132.08 JP19.2@72.644,132.08 74.168,132.08 ; 119.253,88.9 120.777,90.424 v1(120.777,91.567) ; R22.2@122.936,106.934 141.427,106.934 143.764,104.597 143.764,96.52 ; R22.2@123.162,106.708 cw(c123.706,106.164) 123.706,106.934 cw(c123.706,107.704) R22.2@123.162,107.16 ; R22.2@123.341,106.529 cw(c124.319,105.551) 124.319,106.934 cw(c124.319,108.317) R22.2@123.341,107.339 ; v1(123.571,91.567) 131.318,91.567 131.699,91.186 134.665,91.186 134.919,91.44 ; U7.4@134.919,91.948 134.919,91.44 ; U7.8@137.519,91.948 137.519,91.44 137.265,91.186 135.173,91.186 134.919,91.44 ; 140.97,96.52 141.3,96.85 ; 70.995,132.08 cw(c70.995,132.971) 70.365,132.341 ccw(c70.995,132.971) 70.995,132.08 ; 70.995,132.08 ccw(c70.995,131.189) 70.365,131.819 cw(c70.995,131.189) 70.995,132.08 ; 71.14,132.08 cw(c71.14,130.576) 72.203,131.639 ccw(c71.14,130.576) 71.14,132.08 ; 71.14,132.08 ccw(c71.14,133.584) 72.203,132.521 cw(c71.14,133.584) 71.14,132.08 ; 71.608,132.08 cw(c71.608,133.584) 70.545,132.521 ccw(c71.608,133.584) 71.608,132.08 ; 71.608,132.08 ccw(c71.608,130.576) 70.545,131.639 cw(c71.608,130.576) 71.608,132.08 ; 71.753,132.08 cw(c71.753,131.189) 72.383,131.819 ccw(c71.753,131.189) 71.753,132.08 ; 71.753,132.08 ccw(c71.753,132.971) 72.383,132.341 cw(c71.753,132.971) 71.753,132.08 ; 73.535,132.08 cw(c73.535,132.971) 72.905,132.341 ccw(c73.535,132.971) 73.535,132.08 ; 73.535,132.08 ccw(c73.535,131.189) 72.905,131.819 cw(c73.535,131.189) 73.535,132.08 ; 74.148,132.08 cw(c74.148,133.584) 73.085,132.521 ccw(c74.148,133.584) 74.148,132.08 ; 74.148,132.08 ccw(c74.148,130.576) 73.085,131.639 cw(c74.148,130.576) 74.148,132.08
  Top Layer w0.9: U4.2@57.15,92.329 66.548,92.329 BUZZER.0@68.199,93.98
  Top Layer w1: 25.019,38.227 25.146,38.1 BT1.2@33.274,38.1 ; 25.019,57.658 37.084,57.658 38.267,56.475 C5.1@53.213,56.475 56.602,53.086 62.23,53.086 U3.4@64.77,50.546 66.802,50.546 68.072,51.816 68.072,61.849 67.183,62.738 U5.4@65.278,62.738 ; 25.019,73.533 35.687,73.533 37.64,71.58 J1.5@37.717,71.58 ; 25.019,83.058 40.259,83.058 46.101,88.9 D2.1@46.124,88.9 46.124,86.614 ; 25.019,109.22 JP1.3@30.988,109.22 ; 45.313,101.118 46.736,102.542 46.736,105.156 49.012,107.432 ; D3.1@46.124,98.552 49.022,98.552 49.53,98.044 U4.5@49.53,97.409 ; U2.15@49.53,75.438 46.124,78.844 46.124,86.614 ; 7805.1@50.165,109.22 50.165,108.585 49.012,107.432 ; 50.673,105.156 50.673,107.432 ; 51.943,135.509 51.943,129.921 53.721,128.143 53.721,125.349 56.388,122.682 Q3.1@59.436,122.682 ; U4.2@57.15,92.329 55.88,92.329 50.165,86.614 46.124,86.614 ; R3.1@63.881,106.172 61.341,106.172 60.081,107.432 50.673,107.432 ; R6.1@65.913,37.338 65.913,35.052 67.945,33.02 67.945,27.305 ; JP19.1@70.104,132.08 JP19.2@72.644,132.08 JP19.3@75.184,132.08 ; 83.82,135.509 RELAY.0@83.82,141.732 ; U1.20@90.932,80.01 92.115,78.827 C1.2@94.869,78.827 111.8,78.827 U6.7@113.919,76.708 ; C2.1@94.869,58.079 96.052,58.079 97.028,59.055 106.172,59.055 110.998,63.881 110.998,73.787 U6.7@113.919,76.708 ; JP5.1@119.38,77.724 118.364,76.708 U6.7@113.919,76.708 ; 121.881,83.478 R21.1@124.968,83.478 ; 124.968,27.305 JP11.1@124.968,29.464 ; 140.97,96.52 143.764,96.52 154.051,96.52 154.051,36.576 146.939,29.464 ; 46.124,87.693 cw(c47.331,87.693) 46.478,88.546 ccw(c47.331,87.693) 46.124,87.693 ; 46.124,87.693 ccw(c44.917,87.693) 45.77,88.546 cw(c44.917,87.693) 46.124,87.693 ; 47.331,98.552 cw(c47.331,99.759) 46.478,98.906 ccw(c47.331,99.759) 47.331,98.552 ; 47.331,98.552 ccw(c47.331,97.345) 46.478,98.198 cw(c47.331,97.345) 47.331,98.552 ; 49.012,107.432 50.673,107.432 ; 36.997,72.223 ccw(c37.717,72.944) 37.717,71.925 cw(c37.717,72.944) 36.997,72.223 ; 45.231,88.03 cw(c46.124,87.137) 46.124,88.4 ccw(c46.124,87.137) 45.231,88.03 ; 45.287,88.086 ccw(c44.472,88.9) 45.624,88.9 cw(c44.472,88.9) 45.287,88.086 ; 48.705,98.869 cw(c47.313,97.478) 49.28,97.417 ccw(c47.313,97.478) 48.705,98.869 ; 49.329,107.749 ccw(c47.94,109.138) 49.903,109.21 cw(c47.94,109.138) 49.329,107.749 ; 116.324,76.708 ccw(c116.324,80.78) 119.203,77.901 cw(c116.324,80.78) 116.324,76.708 ; 118.738,76.708 ccw(c118.738,78.366) 119.91,77.194 cw(c118.738,78.366) 118.738,76.708
  Top Layer w1.5: JP8.3@29.845,97.028 26.797,97.028 25.019,98.806 ; D3.1@46.124,98.552 46.124,100.307 45.313,101.118 44.577,101.854 25.019,101.854 ; C7.2@49.489,105.156 50.673,105.156 C8.2@52.237,105.156 ; JP19.4@77.724,132.08 JP19.3@75.184,132.08 JP19.2@72.644,132.08 JP19.1@70.104,132.08 70.104,135.509 ; JP5.20@119.38,29.464 119.38,27.305 ; JP5.1@119.38,77.724 121.031,77.724 121.031,82.628 ; 121.881,83.478 121.031,82.628 ; 146.939,29.464 144.78,27.305 124.968,27.305 119.38,27.305 ; 25.019,98.806 25.019,101.854 ; 25.019,98.806 25.019,83.058 25.019,73.533 25.019,57.658 25.019,38.227 25.019,36.703 34.417,27.305 67.945,27.305 119.38,27.305 ; 25.019,101.854 25.019,109.22 25.019,119.38 27.305,121.666 JP9.2@31.242,121.666 31.242,132.588 34.163,135.509 51.943,135.509 70.104,135.509 ; 27.592,121.666 cw(c27.592,118.016) 30.173,120.597 ccw(c27.592,118.016) 27.592,121.666 ; 27.592,121.666 ccw(c27.592,125.316) JP9.2@30.173,122.735 ; 27.592,121.666 ccw(c27.592,125.316) JP9.2@30.173,122.735 ; JP9.2@30.173,122.735 ccw(c27.592,125.316) 31.242,125.316 ; JP9.2@30.173,122.735 ccw(c27.592,125.316) 31.242,125.316 ; 31.242,125.316 ccw(c34.892,125.316) 32.311,122.735 cw(c34.892,125.316) 31.242,125.316 ; 70.104,135.509 83.82,135.509 90.043,135.509 92.837,132.715 92.837,110.744 98.044,105.537 104.394,105.537 107.696,102.235 107.696,93.345 112.141,88.9 119.253,88.9 120.904,87.249 120.904,84.455 121.031,84.328 121.031,82.628
  Bottom Layer w0.254: v1(120.777,91.567) v1(123.571,91.567)
Net7805_0: 7805.0 C7.1 JP22.2 | length 17.3
  Bottom Layer w0.9: 42.291,106.68 43.815,105.156 C7.1@44.489,105.156 ; 42.955,106.016 ccw(c44.489,107.55) C7.1@44.489,105.381
  Bottom Layer w1: JP22.2@35.941,106.68 42.291,106.68 42.418,106.68 44.958,109.22 7805.0@47.625,109.22
NetBT1_1: BT1.1 U3.1 | length 21
  Top Layer w0.254: BT1.1@53.34,38.1 59.944,38.1 U3.1@64.77,42.926 ; BT1.1@53.609,37.831 cw(c54.26,37.18) 54.26,38.1 cw(c54.26,39.02) BT1.1@53.609,38.369 ; BT1.1@53.789,37.651 cw(c54.873,36.567) 54.873,38.1 cw(c54.873,39.633) BT1.1@53.789,38.549 ; U3.1@64.147,42.926 cw(c62.643,42.926) 63.706,41.862 cw(c64.77,40.799) U3.1@64.77,42.303 ; U3.1@64.401,42.926 cw(c63.51,42.926) 64.14,42.296 cw(c64.77,41.666) U3.1@64.77,42.557
NetBUZZER_1: BUZZER.1 Q5.1 | length 15
  Bottom Layer w0.9: BUZZER.1@61.595,93.98 64.008,93.98 67.31,90.678 Q5.1@75.184,90.678
NetC1_1: C1.1 U1.19 Y1.1 | length 21.7
  Top Layer w0.254: U1.19@90.932,76.847 cw(c90.932,75.343) 91.996,76.406 cw(c93.059,77.47) U1.19@91.555,77.47 ; U1.19@90.932,77.101 cw(c90.932,76.21) 91.562,76.84 cw(c92.192,77.47) U1.19@91.301,77.47 ; U1.19@90.932,77.47 94.575,73.827 C1.1@94.869,73.827 94.869,70.764 94.996,70.764 Y1.1@94.996,70.638 ; 93.432,74.97 ccw(c94.869,76.408) C1.1@94.869,74.375 ; 93.865,74.537 ccw(c94.869,75.54) C1.1@94.869,74.121 ; 94.141,74.261 cw(c93.708,73.827) C1.1@94.321,73.827 ; C1.1@94.482,73.439 cw(c93.546,72.504) 94.869,72.504 cw(c96.192,72.504) C1.1@95.256,73.439 ; Y1.1@94.626,71.008 ccw(c94.04,71.594) 94.869,71.594 ccw(c95.952,71.594) Y1.1@95.186,70.828 ; C1.1@94.661,73.619 cw(c94.159,73.117) 94.869,73.117 cw(c95.579,73.117) C1.1@95.077,73.619 ; 94.869,72.207 ccw(c96.565,72.207) Y1.1@95.366,71.008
